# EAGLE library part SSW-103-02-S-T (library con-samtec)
THROUGH-HOLE .025" SQ POST SOCKET Source: Samtec SSW.pdf
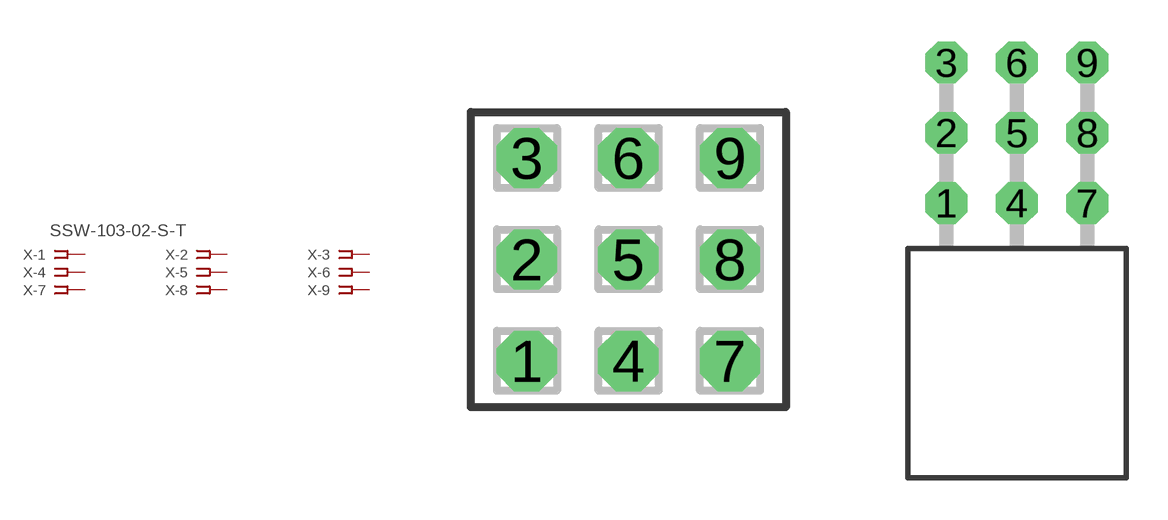
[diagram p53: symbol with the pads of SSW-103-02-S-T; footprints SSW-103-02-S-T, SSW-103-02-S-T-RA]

Designator prefix X; gates -1=FPINV -2=FPIN -3=FPIN -4=FPIN -5=FPIN -6=FPIN -7=FPIN -8=FPIN -9=FPIN

## SSW-103-02-S-T (MPN: SSW-103-02-S-T; OC_FARNELL: unknown; OC_NEWARK: 82P2079)  [SSW-103-02-S-T]
1  -1:1  pas
2  -2:1  pas
3  -3:1  pas
4  -4:1  pas
5  -5:1  pas
6  -6:1  pas
7  -7:1  pas
8  -8:1  pas
9  -9:1  pas

## SSW-103-02-S-TRA (MPN: SSW-103-02-S-T-RA; OC_FARNELL: unknown; OC_NEWARK: 82P2080)  [SSW-103-02-S-T-RA]
Pads as for SSW-103-02-S-T

## Footprint SSW-103-02-S-T (pad centres in mm)
THROUGH-HOLE .025" SQ POST SOCKET Source: Samtec SSW.pdf
drill 1 pad 1.5 octagon: 1 -2.54,-2.54; 2 -2.54,0; 3 -2.54,2.54; 4 0,-2.54; 5 0,0; 6 0,2.54; 7 2.54,-2.54; 8 2.54,0; 9 2.54,2.54

## Footprint SSW-103-02-S-T-RA (pad centres in mm)
THROUGH-HOLE .025" SQ POST SOCKET Source: Samtec SSW.pdf
drill 1 pad 1.5 octagon: 1 -2.54,1.524; 2 -2.54,4.064; 3 -2.54,6.604; 4 0,1.524; 5 0,4.064; 6 0,6.604; 7 2.54,1.524; 8 2.54,4.064; 9 2.54,6.604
